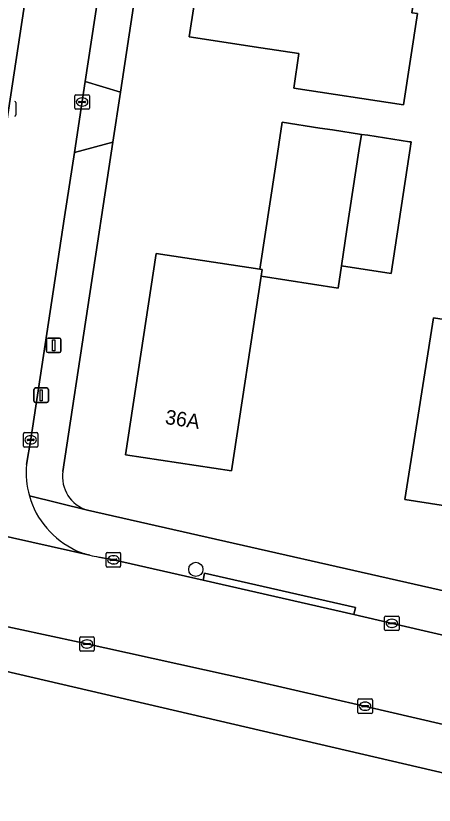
# Model space of a CAD drawing. Extents: x 161483 to 162250, y 379484 to 380833.
# Drawn here: x 161912.9 to 161941.7, y 380393.9 to 380448.4 of the extents above; entities that cross this region are included whole.
import ezdxf

# ---------------------------------------------------------------- set-up
doc = ezdxf.new("R2010")
doc.units = 0
for name, color, linetype in [('IMGEO_Boom', 7, 'Continuous'), ('IMGEO_Erf', 7, 'Continuous'), ('IMGEO_Groenvoorziening', 7, 'Continuous'), ('IMGEO_Kolk', 7, 'Continuous'), ('IMGEO_Lichtmast', 7, 'Continuous'), ('IMGEO_Pand', 7, 'Continuous'), ('IMGEO_Pand_nummerreeks', 7, 'Continuous'), ('IMGEO_Rijbaan_lokaal_open', 7, 'Continuous'), ('IMGEO_Voetpad_open', 7, 'Continuous')]:
    doc.layers.add(name, color=color, linetype=linetype)

msp = doc.modelspace()

# ---------------------------------------------------------------- linework, layer by layer
at = {"layer": 'IMGEO_Boom'}
msp.add_circle((161925.322, 380410.202), 0.489, dxfattribs=at)
at = {"layer": 'IMGEO_Erf'}
for points in [[(161927.815, 380494.701), (161927.546, 380491.983), (161926.64, 380486.015), (161925.725, 380479.996), (161923.046, 380462.355), (161922.159, 380456.515), (161920.124, 380443.114), (161919.599, 380439.661), (161916.152, 380416.963)], [(162078.957, 380365.04), (162051.567, 380370.414), (162025.006, 380376.148), (162000, 380382.025), (161995.099, 380383.252), (161959.315, 380392.214), (161910.21, 380403.651), (161910.18, 380403.657), (161870.617, 380411.917), (161833.133, 380419.277), (161827.383, 380420.325), (161803.575, 380424.662), (161764.511, 380431.266), (161690.732, 380442.772), (161684.352, 380443.733), (161658.891, 380447.568)], [(161917.857, 380414.284), (161947.471, 380407.585), (161980.058, 380399.699)]]:
    msp.add_lwpolyline(points, dxfattribs=at)
for points in [[(161940.212, 380448.585), (161940.588, 380448.528), (161939.632, 380442.245), (161932.069, 380443.396), (161932.43, 380445.769), (161929.811, 380446.167), (161924.867, 380446.92), (161925.98, 380454.228), (161930.924, 380453.475), (161938.516, 380452.319), (161940.729, 380451.982)], [(161934.731, 380440.506), (161936.736, 380440.2), (161937.17, 380440.134), (161940.05, 380439.696), (161940.159, 380439.679), (161938.778, 380430.612), (161935.355, 380431.133), (161935.122, 380429.603), (161929.812, 380430.412), (161927.768, 380416.991), (161920.477, 380418.101), (161922.592, 380431.987), (161929.731, 380430.899), (161930.806, 380437.959), (161931.274, 380441.032), (161933.874, 380440.636)], [(161952.245, 380425.957), (161955.23, 380425.489), (161954.029, 380417.835), (161953.254, 380412.895), (161946.49, 380413.957), (161939.727, 380415.018), (161940.502, 380419.958), (161941.693, 380427.544), (161944.773, 380427.061), (161944.298, 380424.033), (161947.982, 380423.455), (161948.072, 380424.03), (161948.467, 380426.549)]]:
    msp.add_lwpolyline(points, close=True, dxfattribs=at)
msp.add_arc((161918.544, 380416.603), 2.419, 171.4456, 253.5023, dxfattribs=at)
at = {"layer": 'IMGEO_Groenvoorziening'}
msp.add_lwpolyline([(161908.667, 380417.626), (161909.61, 380423.559), (161913.458, 380448.83), (161916.269, 380467.244), (161913.37, 380467.67), (161912.348, 380460.87), (161908.746, 380436.913), (161905.92, 380418.115)], close=True, dxfattribs=at)
at = {"layer": 'IMGEO_Kolk'}
for p, q in [((161916.982, 380442.007), (161916.982, 380442.859)), ((161917.057, 380442.933), (161917.909, 380442.933)), ((161917.47, 380442.713), (161917.495, 380442.713)), ((161917.983, 380442.859), (161917.983, 380442.007)), ((161912.912, 380442.39), (161912.912, 380441.538)), ((161917.241, 380442.427), (161917.241, 380442.439)), ((161917.679, 380442.39), (161917.281, 380442.39)), ((161917.284, 380442.476), (161917.682, 380442.476)), ((161917.493, 380442.153), (161917.468, 380442.153)), ((161917.725, 380442.439), (161917.725, 380442.427)), ((161917.909, 380441.933), (161917.057, 380441.933)), ((161913.438, 380418.709), (161913.438, 380419.561)), ((161913.513, 380419.635), (161914.365, 380419.635)), ((161913.926, 380419.415), (161913.951, 380419.415)), ((161914.439, 380419.561), (161914.439, 380418.709)), ((161913.697, 380419.129), (161913.697, 380419.141)), ((161914.135, 380419.092), (161913.737, 380419.092)), ((161913.74, 380419.178), (161914.138, 380419.178)), ((161913.949, 380418.855), (161913.924, 380418.855)), ((161914.181, 380419.141), (161914.181, 380419.129)), ((161914.365, 380418.635), (161913.513, 380418.635)), ((161919.138, 380410.437), (161919.138, 380411.289)), ((161919.213, 380411.363), (161920.065, 380411.363)), ((161919.626, 380411.143), (161919.651, 380411.143)), ((161920.139, 380411.289), (161920.139, 380410.437)), ((161919.397, 380410.857), (161919.397, 380410.869)), ((161919.835, 380410.82), (161919.437, 380410.82)), ((161919.44, 380410.906), (161919.838, 380410.906)), ((161919.649, 380410.583), (161919.624, 380410.583)), ((161919.881, 380410.869), (161919.881, 380410.857)), ((161920.065, 380410.363), (161919.213, 380410.363)), ((161938.332, 380406.058), (161938.332, 380406.91)), ((161938.407, 380406.984), (161939.259, 380406.984)), ((161938.82, 380406.764), (161938.845, 380406.764)), ((161939.333, 380406.91), (161939.333, 380406.058)), ((161938.591, 380406.478), (161938.591, 380406.49)), ((161939.029, 380406.441), (161938.631, 380406.441)), ((161938.634, 380406.527), (161939.032, 380406.527)), ((161938.843, 380406.204), (161938.818, 380406.204)), ((161939.075, 380406.49), (161939.075, 380406.478)), ((161939.259, 380405.984), (161938.407, 380405.984)), ((161917.319, 380404.633), (161917.319, 380405.485)), ((161917.394, 380405.559), (161918.246, 380405.559)), ((161917.578, 380405.053), (161917.578, 380405.065)), ((161917.621, 380405.102), (161918.019, 380405.102)), ((161917.807, 380405.339), (161917.832, 380405.339)), ((161918.062, 380405.065), (161918.062, 380405.053)), ((161918.32, 380405.485), (161918.32, 380404.633)), ((161918.246, 380404.559), (161917.394, 380404.559)), ((161918.016, 380405.016), (161917.618, 380405.016)), ((161917.83, 380404.779), (161917.805, 380404.779)), ((161936.562, 380401.267), (161937.414, 380401.267)), ((161936.487, 380400.341), (161936.487, 380401.193)), ((161936.746, 380400.761), (161936.746, 380400.773)), ((161937.184, 380400.724), (161936.786, 380400.724)), ((161936.789, 380400.81), (161937.187, 380400.81)), ((161936.975, 380401.047), (161937, 380401.047)), ((161937.23, 380400.773), (161937.23, 380400.761)), ((161937.488, 380401.193), (161937.488, 380400.341)), ((161937.414, 380400.267), (161936.562, 380400.267)), ((161936.998, 380400.487), (161936.973, 380400.487))]:
    msp.add_line(p, q, dxfattribs=at)
for points in [[(161916.982, 380442.007), (161916.982, 380442.859)], [(161917.057, 380442.933), (161917.909, 380442.933)], [(161917.983, 380442.859), (161917.983, 380442.007)], [(161912.912, 380442.39), (161912.912, 380441.538)], [(161917.909, 380441.933), (161917.057, 380441.933)], [(161913.438, 380418.709), (161913.438, 380419.561)], [(161913.513, 380419.635), (161914.365, 380419.635)], [(161914.439, 380419.561), (161914.439, 380418.709)], [(161914.365, 380418.635), (161913.513, 380418.635)], [(161919.138, 380410.437), (161919.138, 380411.289)], [(161919.213, 380411.363), (161920.065, 380411.363)], [(161920.139, 380411.289), (161920.139, 380410.437)], [(161920.065, 380410.363), (161919.213, 380410.363)], [(161938.332, 380406.058), (161938.332, 380406.91)], [(161938.407, 380406.984), (161939.259, 380406.984)], [(161939.333, 380406.91), (161939.333, 380406.058)], [(161939.259, 380405.984), (161938.407, 380405.984)], [(161917.319, 380404.633), (161917.319, 380405.485)], [(161917.394, 380405.559), (161918.246, 380405.559)], [(161918.32, 380405.485), (161918.32, 380404.633)], [(161918.246, 380404.559), (161917.394, 380404.559)], [(161936.562, 380401.267), (161937.414, 380401.267)], [(161936.487, 380400.341), (161936.487, 380401.193)], [(161937.488, 380401.193), (161937.488, 380400.341)], [(161937.414, 380400.267), (161936.562, 380400.267)]]:
    msp.add_lwpolyline(points, dxfattribs=at)
for centre, radius, start, end in [((161917.059, 380442.857), 0.0765, 91.552, 178.448), ((161917.059, 380442.857), 0.0765, 91.552, 178.448), ((161917.907, 380442.857), 0.0765, 1.552, 88.448), ((161917.907, 380442.857), 0.0765, 1.552, 88.448), ((161912.836, 380442.388), 0.0765, 1.552, 88.448), ((161912.836, 380442.388), 0.0765, 1.552, 88.448), ((161917.281, 380442.436), 0.0403, 85.8775, 175.7526), ((161917.278, 380442.426), 0.0366, 178.938, 274.7102), ((161917.682, 380442.433), 0.043, 264.8664, 352.4533), ((161917.686, 380442.438), 0.0386, 1.7309, 96.639), ((161912.836, 380441.54), 0.0765, 271.552, 358.448), ((161912.836, 380441.54), 0.0765, 271.552, 358.448), ((161917.059, 380442.009), 0.0765, 181.552, 268.448), ((161917.059, 380442.009), 0.0765, 181.552, 268.448), ((161917.907, 380442.009), 0.0765, 271.552, 358.448), ((161917.907, 380442.009), 0.0765, 271.552, 358.448), ((161913.515, 380419.559), 0.0765, 91.552, 178.448), ((161913.515, 380419.559), 0.0765, 91.552, 178.448), ((161914.363, 380419.559), 0.0765, 1.552, 88.448), ((161914.363, 380419.559), 0.0765, 1.552, 88.448), ((161913.515, 380418.711), 0.0765, 181.552, 268.448), ((161913.515, 380418.711), 0.0765, 181.552, 268.448), ((161913.737, 380419.138), 0.0403, 85.8775, 175.7526), ((161913.734, 380419.128), 0.0366, 178.938, 274.7102), ((161914.138, 380419.135), 0.043, 264.8664, 352.4533), ((161914.142, 380419.14), 0.0386, 1.7309, 96.639), ((161914.363, 380418.711), 0.0765, 271.552, 358.448), ((161914.363, 380418.711), 0.0765, 271.552, 358.448), ((161919.215, 380411.287), 0.0765, 91.552, 178.448), ((161919.215, 380411.287), 0.0765, 91.552, 178.448), ((161920.063, 380411.287), 0.0765, 1.552, 88.448), ((161920.063, 380411.287), 0.0765, 1.552, 88.448), ((161919.437, 380410.866), 0.0403, 85.8775, 175.7526), ((161919.434, 380410.856), 0.0366, 178.938, 274.7102), ((161919.838, 380410.863), 0.043, 264.8664, 352.4533), ((161919.842, 380410.868), 0.0386, 1.7309, 96.639), ((161919.215, 380410.439), 0.0765, 181.552, 268.448), ((161919.215, 380410.439), 0.0765, 181.552, 268.448), ((161920.063, 380410.439), 0.0765, 271.552, 358.448), ((161920.063, 380410.439), 0.0765, 271.552, 358.448), ((161938.409, 380406.908), 0.0765, 91.552, 178.448), ((161938.409, 380406.908), 0.0765, 91.552, 178.448), ((161939.257, 380406.908), 0.0765, 1.552, 88.448), ((161939.257, 380406.908), 0.0765, 1.552, 88.448), ((161938.631, 380406.487), 0.0403, 85.8775, 175.7526), ((161938.628, 380406.477), 0.0366, 178.938, 274.7102), ((161939.032, 380406.484), 0.043, 264.8664, 352.4533), ((161939.036, 380406.489), 0.0386, 1.7309, 96.639), ((161938.409, 380406.06), 0.0765, 181.552, 268.448), ((161938.409, 380406.06), 0.0765, 181.552, 268.448), ((161939.257, 380406.06), 0.0765, 271.552, 358.448), ((161939.257, 380406.06), 0.0765, 271.552, 358.448), ((161917.396, 380405.483), 0.0765, 91.552, 178.448), ((161917.396, 380405.483), 0.0765, 91.552, 178.448), ((161917.618, 380405.062), 0.0403, 85.8775, 175.7526), ((161917.615, 380405.052), 0.0366, 178.938, 274.7102), ((161918.019, 380405.059), 0.043, 264.8664, 352.4533), ((161918.023, 380405.064), 0.0386, 1.7309, 96.639), ((161918.244, 380405.483), 0.0765, 1.552, 88.448), ((161918.244, 380405.483), 0.0765, 1.552, 88.448), ((161917.396, 380404.635), 0.0765, 181.552, 268.448), ((161917.396, 380404.635), 0.0765, 181.552, 268.448), ((161918.244, 380404.635), 0.0765, 271.552, 358.448), ((161918.244, 380404.635), 0.0765, 271.552, 358.448), ((161936.564, 380401.191), 0.0765, 91.552, 178.448), ((161936.564, 380401.191), 0.0765, 91.552, 178.448), ((161937.412, 380401.191), 0.0765, 1.552, 88.448), ((161937.412, 380401.191), 0.0765, 1.552, 88.448), ((161936.786, 380400.77), 0.0403, 85.8775, 175.7526), ((161936.783, 380400.76), 0.0366, 178.938, 274.7102), ((161937.187, 380400.767), 0.043, 264.8664, 352.4533), ((161937.191, 380400.772), 0.0386, 1.7309, 96.639), ((161936.564, 380400.343), 0.0765, 181.552, 268.448), ((161936.564, 380400.343), 0.0765, 181.552, 268.448), ((161937.412, 380400.343), 0.0765, 271.552, 358.448), ((161937.412, 380400.343), 0.0765, 271.552, 358.448)]:
    msp.add_arc(centre, radius, start, end, dxfattribs=at)
for centre, major_axis, ratio, start_param, end_param in [((161917.469, 380442.433), (-0.387, 0.002), 0.722429, 4.712389, 7.853982), ((161917.494, 380442.433), (-0.39, 0.002), 0.717154, 1.570796, 4.712389), ((161913.925, 380419.135), (-0.387, 0.002), 0.722429, 4.712389, 7.853982), ((161913.95, 380419.135), (-0.39, 0.002), 0.717154, 1.570796, 4.712389), ((161919.625, 380410.863), (-0.387, 0.002), 0.722429, 4.712389, 7.853982), ((161919.65, 380410.863), (-0.39, 0.002), 0.717154, 1.570796, 4.712389), ((161938.819, 380406.484), (-0.387, 0.002), 0.722429, 4.712389, 7.853982), ((161938.844, 380406.484), (-0.39, 0.002), 0.717154, 1.570796, 4.712389), ((161917.806, 380405.059), (-0.387, 0.002), 0.722429, 4.712389, 7.853982), ((161917.831, 380405.059), (-0.39, 0.002), 0.717154, 1.570796, 4.712389), ((161936.974, 380400.767), (-0.387, 0.002), 0.722429, 4.712389, 7.853982), ((161936.999, 380400.767), (-0.39, 0.002), 0.717154, 1.570796, 4.712389)]:
    msp.add_ellipse(centre, major_axis=major_axis, ratio=ratio, start_param=start_param, end_param=end_param, dxfattribs=at)
at = {"layer": 'IMGEO_Lichtmast'}
for p, q in [((161915.033, 380425.254), (161915.033, 380426.054)), ((161915.033, 380426.054), (161915.033, 380425.254)), ((161915.133, 380426.154), (161915.923, 380426.154)), ((161915.923, 380426.154), (161915.133, 380426.154)), ((161916.023, 380426.054), (161916.023, 380425.254)), ((161916.023, 380425.254), (161916.023, 380426.054)), ((161915.923, 380425.154), (161915.133, 380425.154)), ((161915.133, 380425.154), (161915.923, 380425.154)), ((161914.165, 380421.812), (161914.165, 380422.612)), ((161914.165, 380422.612), (161914.165, 380421.812)), ((161914.265, 380422.712), (161915.055, 380422.712)), ((161915.055, 380422.712), (161914.265, 380422.712)), ((161915.155, 380422.612), (161915.155, 380421.812)), ((161915.155, 380421.812), (161915.155, 380422.612)), ((161915.055, 380421.712), (161914.265, 380421.712)), ((161914.265, 380421.712), (161915.055, 380421.712))]:
    msp.add_line(p, q, dxfattribs=at)
for points in [[(161915.453, 380426.029), (161915.603, 380426.029), (161915.603, 380425.279), (161915.453, 380425.279), (161915.453, 380426.029)], [(161914.585, 380422.587), (161914.735, 380422.587), (161914.735, 380421.837), (161914.585, 380421.837), (161914.585, 380422.587)]]:
    msp.add_lwpolyline(points, dxfattribs=at)
for centre, start, end in [((161915.133, 380426.054), 90, 180), ((161915.133, 380426.054), 90, 180), ((161915.923, 380426.054), 0, 90), ((161915.923, 380426.054), 360, 90), ((161915.133, 380425.254), 180, 270), ((161915.133, 380425.254), 180, 270), ((161915.923, 380425.254), 270, 0), ((161915.923, 380425.254), 270, 0), ((161914.265, 380422.612), 90, 180), ((161914.265, 380422.612), 90, 180), ((161915.055, 380422.612), 0, 90), ((161915.055, 380422.612), 360, 90), ((161914.265, 380421.812), 180, 270), ((161914.265, 380421.812), 180, 270), ((161915.055, 380421.812), 270, 0), ((161915.055, 380421.812), 270, 0)]:
    msp.add_arc(centre, 0.1, start, end, dxfattribs=at)
at = {"layer": 'IMGEO_Pand'}
for points in [[(161939.632, 380442.245), (161940.588, 380448.528), (161940.212, 380448.585), (161940.729, 380451.982), (161938.516, 380452.319), (161930.924, 380453.475), (161925.98, 380454.228), (161924.867, 380446.92), (161929.811, 380446.167), (161932.43, 380445.769), (161932.069, 380443.396)], [(161936.736, 380440.2), (161934.731, 380440.506), (161933.874, 380440.636), (161931.274, 380441.032), (161930.806, 380437.959), (161929.731, 380430.899), (161929.883, 380430.876), (161929.812, 380430.412), (161935.122, 380429.603), (161935.355, 380431.133), (161935.736, 380433.633), (161936.563, 380439.067)], [(161936.736, 380440.2), (161936.563, 380439.067), (161935.736, 380433.633), (161935.355, 380431.133), (161938.778, 380430.612), (161940.159, 380439.679), (161940.05, 380439.696), (161937.17, 380440.134)], [(161929.812, 380430.412), (161929.883, 380430.876), (161929.731, 380430.899), (161922.592, 380431.987), (161920.477, 380418.101), (161927.768, 380416.991)], [(161947.982, 380423.455), (161944.298, 380424.033), (161944.773, 380427.061), (161941.693, 380427.544), (161940.502, 380419.958), (161939.727, 380415.018), (161946.49, 380413.957)]]:
    msp.add_lwpolyline(points, close=True, dxfattribs=at)
at = {"layer": 'IMGEO_Rijbaan_lokaal_open'}
for points in [[(161920.218, 380493.077), (161920.146, 380492.723), (161919.219, 380486.625), (161918.352, 380480.926), (161916.839, 380470.975), (161916.636, 380469.648), (161916.269, 380467.244), (161913.458, 380448.83), (161909.61, 380423.559), (161908.667, 380417.626)], [(161913.655, 380417.428), (161913.944, 380419.175), (161916.279, 380434.508), (161916.954, 380438.957), (161917.695, 380443.841), (161919.434, 380455.31)], [(161918.01, 380411.187), (161891.545, 380417.125)], [(161891.545, 380417.125), (161918.01, 380411.187)], [(161874.467, 380414.355), (161883.757, 380412.463), (161890.276, 380411.034), (161891.722, 380410.719), (161896.731, 380409.629), (161905.094, 380407.809), (161910.844, 380406.568), (161917.277, 380405.18), (161929.239, 380402.532), (161937.036, 380400.757), (161943.985, 380399.147), (161945.872, 380398.697), (161948.892, 380397.978), (161955.767, 380396.34), (161968.876, 380393.146)], [(161938.867, 380406.475), (161936.208, 380407.084), (161925.821, 380409.464), (161919.635, 380410.863), (161918.642, 380411.053)], [(161992.46, 380393.44), (161987.286, 380394.727), (161983.129, 380395.815), (161979.272, 380396.825), (161979.053, 380396.866), (161968.34, 380399.467), (161960.942, 380401.274), (161954.267, 380402.904), (161938.867, 380406.475)]]:
    msp.add_lwpolyline(points, dxfattribs=at)
for centre, radius, start, end in [((161919.512, 380416.868), 5.884, 174.542, 195.7414), ((161919.523, 380416.871), 5.895, 195.7376, 245.2813), ((161919.604, 380417.341), 6.357, 246.3913, 255.4796), ((161919.638, 380417.309), 6.335, 255.1064, 260.9519)]:
    msp.add_arc(centre, radius, start, end, dxfattribs=at)
at = {"layer": 'IMGEO_Voetpad_open'}
for points in [[(161919.434, 380455.31), (161917.695, 380443.841), (161920.124, 380443.114), (161922.159, 380456.515)], [(161919.599, 380439.661), (161920.124, 380443.114), (161917.695, 380443.841), (161916.954, 380438.957)], [(161925.821, 380409.464), (161936.208, 380407.084), (161936.313, 380407.572), (161925.926, 380409.952)]]:
    msp.add_lwpolyline(points, close=True, dxfattribs=at)
for points in [[(161919.599, 380439.661), (161916.954, 380438.957), (161916.279, 380434.508), (161913.944, 380419.175), (161913.655, 380417.428)], [(161916.152, 380416.963), (161919.599, 380439.661)], [(161947.471, 380407.585), (161917.857, 380414.284), (161913.849, 380415.272)], [(161913.849, 380415.272), (161917.857, 380414.284)], [(161918.642, 380411.053), (161919.635, 380410.863), (161925.821, 380409.464), (161925.926, 380409.952), (161936.313, 380407.572), (161936.208, 380407.084), (161938.867, 380406.475), (161954.267, 380402.904), (161954.379, 380403.391), (161961.054, 380401.761), (161960.942, 380401.274), (161968.34, 380399.467), (161979.053, 380396.866), (161979.272, 380396.825), (161983.129, 380395.815), (161983.252, 380396.299), (161992.583, 380393.924)], [(161948.892, 380397.978), (161948.777, 380397.492), (161945.757, 380398.211), (161945.872, 380398.697), (161943.985, 380399.147), (161937.036, 380400.757), (161929.239, 380402.532), (161917.277, 380405.18), (161910.844, 380406.568), (161910.744, 380406.079), (161910.18, 380403.657), (161910.21, 380403.651), (161959.315, 380392.214)]]:
    msp.add_lwpolyline(points, dxfattribs=at)
for centre, radius, start, end in [((161919.512, 380416.868), 5.884, 174.542, 195.7414), ((161918.544, 380416.603), 2.419, 171.4456, 253.5023), ((161919.523, 380416.871), 5.895, 195.7376, 245.2813), ((161919.604, 380417.341), 6.357, 246.3913, 255.4796), ((161919.638, 380417.309), 6.335, 255.1064, 260.9519)]:
    msp.add_arc(centre, radius, start, end, dxfattribs=at)

# ---------------------------------------------------------------- texts
at = {"layer": 'IMGEO_Pand_nummerreeks'}
msp.add_text('36A', height=1, rotation=351.3426, dxfattribs=at).set_placement((161923.161, 380420.241))

doc.saveas('drawing.dxf')
